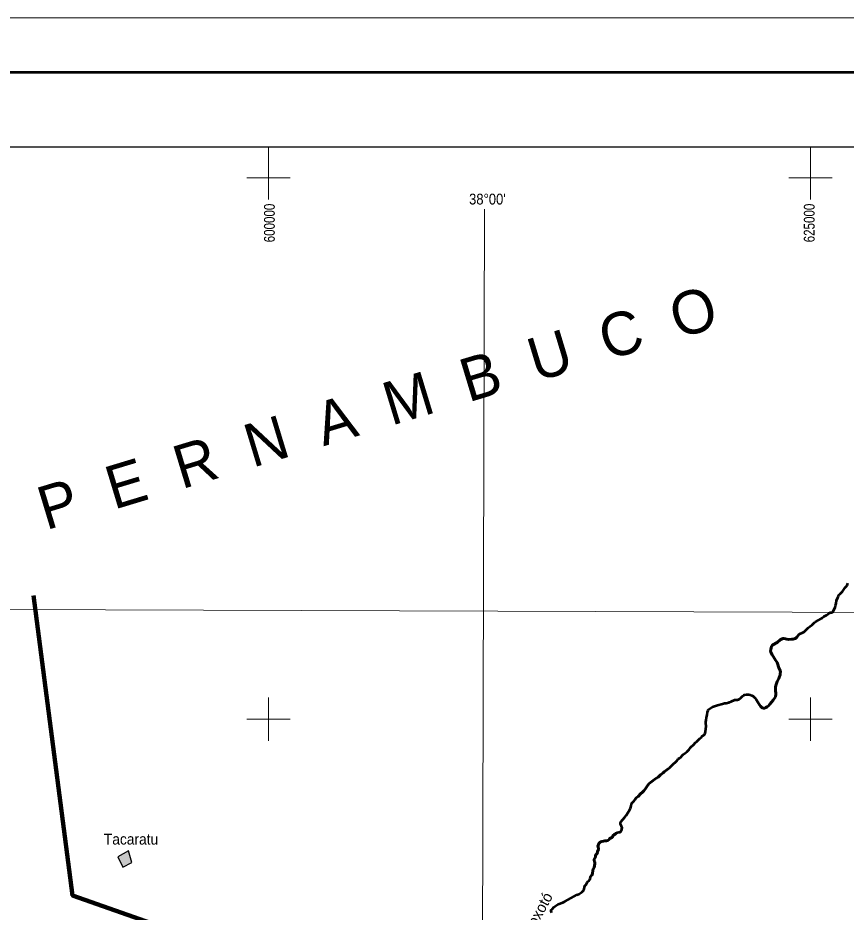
# Model space of a CAD drawing. Extents: x 553962 to 842807, y 8883888 to 9032388.
# Drawn here: x 588436 to 626649, y 8991098 to 9032388 of the extents above; entities that cross this region are included whole.
import ezdxf
from ezdxf.enums import TextEntityAlignment as Align

# ---------------------------------------------------------------- set-up
doc = ezdxf.new("R2010")
doc.units = 0
doc.header["$LTSCALE"] = 150
doc.linetypes.add('LONG_DASH_SHORT_DASH', pattern=[9.9, 6, -1.2, 1.5, -1.2])
for name, color, linetype, lineweight in [('1', 7, 'Continuous', 13), ('2', 7, 'Continuous', 13), ('21', 7, 'Continuous', 25), ('24', 7, 'Continuous', 25), ('3', 7, 'Continuous', 13), ('7', 7, 'LONG_DASH_SHORT_DASH', 60), ('9', 7, 'Continuous', 90)]:
    doc.layers.add(name, color=color, linetype=linetype, lineweight=lineweight)
for name, color, linetype in [('41', 7, 'Continuous'), ('42', 7, 'Continuous'), ('46', 7, 'Continuous'), ('47', 7, 'Continuous'), ('49', 7, 'Continuous')]:
    doc.layers.add(name, color=color, linetype=linetype)

msp = doc.modelspace()

# ---------------------------------------------------------------- hatches: boundary and pattern name
at = {"layer": '21'}
msp.add_hatch(color=256, dxfattribs=at).paths.add_polyline_path([(593047.1, 8993652.8), (593274.2, 8993173.1), (593688.7, 8993391.5), (593540, 8993932.9)])

# ---------------------------------------------------------------- linework, layer by layer
at = {"layer": '1'}
for points in [[(609971.9, 9023551.8), (609764.7, 8949706.7), (609734.2, 8939404.4)], [(565303.2, 9005146.6), (664889.8, 9004806.7), (719872.1, 9004543.9), (790635.8, 9004109)]]:
    msp.add_lwpolyline(points, dxfattribs=at)
at = {"layer": '2'}
for p, q in [((600000, 9024000), (600000, 9026438.8)), ((625000, 9024000), (625000, 9026438.8)), ((599000, 9025000), (601000, 9025000)), ((624000, 9025000), (626000, 9025000)), ((600000, 8999000), (600000, 9001000)), ((625000, 8999000), (625000, 9001000)), ((599000, 9000000), (601000, 9000000)), ((624000, 9000000), (626000, 9000000))]:
    msp.add_line(p, q, dxfattribs=at)
at = {"layer": '21'}
msp.add_lwpolyline([(593047.1, 8993652.8), (593274.2, 8993173.1), (593688.7, 8993391.5), (593540, 8993932.9)], close=True, dxfattribs=at)
at = {"layer": '24', "lineweight": 53}
for points in [[(626161, 9005249.2), (626188.6, 9005351.8), (626211.6, 9005488.2), (626262, 9005622), (626290.8, 9005686), (626318.1, 9005740.6), (626357.2, 9005784), (626440.5, 9005861.4), (626481.1, 9005905.8), (626516.3, 9005951), (626547.5, 9005998.1), (626576.5, 9006046.2), (626606.6, 9006087.7), (626651.3, 9006133.9), (626697.2, 9006185.8), (626721.1, 9006227.2), (626725, 9006288.4)], [(626020.3, 9004931.6), (626138.4, 9005165.4), (626161, 9005249.2)], [(624968.7, 9004287.4), (625077.4, 9004367.4), (625125.3, 9004407.4), (625196.1, 9004475.4), (625232, 9004503.4), (625369.3, 9004583.4), (625507, 9004648.4), (625552.2, 9004680.4), (625627.3, 9004743.4), (625747.5, 9004813.4), (625804.8, 9004859.3), (625863.6, 9004898.3), (625936.5, 9004925.7), (626020.3, 9004931.6)], [(622356.1, 9001071.6), (622438.9, 9000988.6), (622501.2, 9000910.6), (622651.6, 9000673.6), (622694.8, 9000613.6), (622741.9, 9000562.6), (622781.6, 9000528.6), (622838, 9000513.6), (622887.5, 9000510.6), (622903.5, 9000513.6), (622951.5, 9000538.6), (623008.3, 9000580.6), (623061.1, 9000626.5), (623124.5, 9000694.5), (623279.2, 9000880.5), (623385, 9001031.5), (623398.2, 9001059.5), (623411.2, 9001147.5), (623406.1, 9001224.5), (623394.5, 9001300.5), (623396.9, 9001485.5), (623407.8, 9001557.5), (623420.7, 9001604.5), (623474.8, 9001753.5), (623546.5, 9001882.5), (623566.5, 9001928.5), (623606.4, 9002057.5), (623614.4, 9002114.5), (623615.2, 9002180.5), (623603.6, 9002252.5), (623548.9, 9002380.5), (623488.7, 9002579.5), (623465.3, 9002623.5), (623431.2, 9002675.5), (623387.3, 9002730.5), (623302, 9002882.5), (623235.1, 9002973.5), (623183.3, 9003094.5), (623167.7, 9003160.5), (623170, 9003229.5), (623186.6, 9003301.5), (623210, 9003362.5), (623241.9, 9003412.5), (623274.8, 9003442.5), (623462.1, 9003547.5), (623608.8, 9003667.5), (623666.2, 9003700.5), (623727.2, 9003726.5), (623755.6, 9003733.5), (623782.5, 9003731.5), (623993.5, 9003691.5), (624127.2, 9003701.5), (624209, 9003698.5), (624301.4, 9003736.4), (624324.7, 9003751.4), (624377.4, 9003798.4), (624433, 9003873.4), (624469.5, 9003912.4), (624514.8, 9003941.4), (624628.9, 9003992.4), (624709.5, 9004038.4), (624743.9, 9004077.4), (624810.6, 9004137.4), (624900.3, 9004230.4), (624968, 9004288.4)], [(620148.3, 8999353.7), (620168.6, 8999417.7), (620186.8, 8999678.7), (620178.1, 8999819.7), (620178.5, 8999880.7), (620194.3, 8999957.7), (620208.2, 9000078.7), (620242.8, 9000202.7), (620252.9, 9000329.7), (620263.2, 9000378.7), (620280.1, 9000412.7), (620305.3, 9000447.7), (620344.5, 9000485.7), (620432.6, 9000539.7), (620488.9, 9000569.7), (620581.6, 9000610.7), (620710.5, 9000657.7), (620939.4, 9000718.7), (621042.2, 9000740.6), (621118.4, 9000748.6), (621242.2, 9000776.6), (621275.5, 9000790.6), (621342.1, 9000826.6), (621518.2, 9000894.6), (621561.1, 9000901.6), (621637.2, 9000903.6), (621689.6, 9000916.6), (621716.6, 9000931.6), (621774.6, 9000977.6), (621867.2, 9001066.6), (621924.7, 9001110.6), (621967.5, 9001129.6), (622048.6, 9001140.6), (622160.3, 9001143.6), (622215.2, 9001136.6), (622300.1, 9001105.6), (622356.1, 9001071.6)], [(616275, 8994855), (616299.8, 8994916), (616306.6, 8994947), (616309.5, 8994997), (616289.9, 8995061), (616239.9, 8995143), (616235.6, 8995179), (616237.4, 8995206), (616262.8, 8995260), (616352.4, 8995378.9), (616439.6, 8995482.9), (616497.8, 8995558.9), (616654.6, 8995808.9), (616704.2, 8995904.9), (616721.4, 8995949.9), (616734.9, 8996009.9), (616742.4, 8996094.9), (616755.2, 8996130.9), (616770.5, 8996150.9), (616865.5, 8996231.9), (616968.5, 8996369.9), (617050.4, 8996439.9), (617160.7, 8996559.9), (617252.1, 8996633.9), (617320.9, 8996701.9), (617376, 8996767.9), (617466.2, 8996912.9), (617553.7, 8997026.9), (617627.5, 8997088.9), (617747.7, 8997167.8), (617821.7, 8997231.8), (617864.4, 8997264.8), (617970.3, 8997332.8), (618086, 8997441.8), (618201.6, 8997530.8), (618257.2, 8997582.8), (618380.8, 8997669.8), (618495.1, 8997763.8), (618608.2, 8997867.8), (618687.2, 8997947.8), (618784.2, 8998026.8), (618847.8, 8998091.8), (618880.8, 8998148.8), (618904.8, 8998177.8), (618927, 8998194.8), (618960.5, 8998211.8), (619017, 8998253.8), (619099.7, 8998350.8), (619132.8, 8998382.8), (619235.9, 8998457.8), (619310.3, 8998518.8), (619402.8, 8998610.8), (619472.9, 8998704.8), (619501.7, 8998736.7), (619608.1, 8998826.7), (619700.3, 8998928.7), (619746.9, 8998966.7), (619804.3, 8999021.7), (619907.6, 8999106.7), (619970.1, 8999177.7), (620010.3, 8999215.7), (620083.8, 8999267.7), (620109.1, 8999292.7), (620148.3, 8999353.7), (620148.3, 8999353.7)], [(615088.6, 8993660), (615092.1, 8993720), (615153, 8993790), (615174.6, 8993852), (615175.1, 8993904), (615179, 8993921), (615187.3, 8993934), (615211.5, 8993958), (615228.8, 8993992), (615227.7, 8994030), (615203.4, 8994096), (615199.3, 8994145), (615206.1, 8994178), (615239.1, 8994264), (615295.5, 8994325), (615320, 8994336), (615520.9, 8994382), (615601.5, 8994383), (615661.9, 8994403), (615699.6, 8994431), (615734.4, 8994474), (615755.4, 8994494), (615812.3, 8994527), (615840.8, 8994550), (615864.4, 8994578), (615900.1, 8994637), (615919.4, 8994659), (615934.8, 8994670), (615988.9, 8994692), (616008.8, 8994710), (616037.3, 8994745), (616076.4, 8994766), (616108.6, 8994778), (616169.1, 8994784), (616218.9, 8994795), (616250.2, 8994821), (616275, 8994855)], [(613066.1, 8991064.2), (613044.7, 8991133.2), (613043.4, 8991164.2), (613047.9, 8991196.2), (613081.7, 8991228.2), (613169.8, 8991332.2), (613227.7, 8991376.2), (613365.8, 8991458.1), (613579.6, 8991541.1), (613666.1, 8991582.1), (614090.8, 8991825.1), (614218.9, 8991891.1), (614310.9, 8991932.1), (614460.7, 8992023.1), (614532.5, 8992094.1), (614543.7, 8992113.1), (614569, 8992177.1), (614582, 8992234.1), (614589.2, 8992317.1), (614668.2, 8992394.1), (614704.5, 8992469.1), (614728, 8992505.1), (614788.8, 8992558.1), (614827.1, 8992602.1), (614841.2, 8992635.1), (614852.2, 8992705.1), (614861.2, 8992733.1), (614874, 8992755.1), (614920, 8992803.1), (614934.5, 8992832.1), (614943.5, 8992879.1), (614957.9, 8993016), (614981.1, 8993081), (615017.2, 8993154), (615053.5, 8993321), (615053.4, 8993409), (615046.2, 8993436), (615020.3, 8993489), (615020.7, 8993515), (615030.5, 8993541), (615082.9, 8993633), (615082.9, 8993633), (615088.6, 8993660)]]:
    msp.add_lwpolyline(points, dxfattribs=at)
at = {"layer": '3'}
msp.add_lwpolyline([(842807.3, 9032387.8), (842807.3, 8883887.8), (553961.7, 8883887.8), (553961.7, 9032387.8)], close=True, dxfattribs=at)
at = {"layer": '3', "lineweight": 53}
msp.add_lwpolyline([(840307.3, 9029887.8), (840307.3, 8886387.8), (560211.7, 8886387.8), (560211.7, 9029887.8)], close=True, dxfattribs=at)
at = {"layer": '3', "lineweight": 25}
msp.add_lwpolyline([(563033.9, 9026438.8), (793061.1, 9026438.8), (793495.6, 8889836.8), (563468.3, 8889836.8)], close=True, dxfattribs=at)
at = {"layer": '7'}
for points in [[(622572.2, 9000798.7), (622651.6, 9000673.6), (622694.8, 9000613.6), (622741.9, 9000562.6), (622781.6, 9000528.6), (622838, 9000513.6), (622887.5, 9000510.6), (622903.5, 9000513.6), (622951.5, 9000538.6), (623008.3, 9000580.6), (623061.1, 9000626.5), (623124.5, 9000694.5), (623279.2, 9000880.5), (623385, 9001031.5), (623398.2, 9001059.5), (623411.2, 9001147.5), (623406.1, 9001224.5), (623394.5, 9001300.5), (623396.9, 9001485.5), (623407.8, 9001557.5), (623420.7, 9001604.5), (623474.8, 9001753.5), (623546.5, 9001882.5), (623566.5, 9001928.5), (623606.4, 9002057.5), (623614.4, 9002114.5), (623615.2, 9002180.5), (623603.6, 9002252.5), (623548.9, 9002380.5), (623488.7, 9002579.5), (623465.3, 9002623.5), (623431.2, 9002675.5), (623387.3, 9002730.5), (623302, 9002882.5), (623235.1, 9002973.5), (623183.3, 9003094.5), (623167.7, 9003160.5), (623170, 9003229.5), (623186.6, 9003301.5), (623210, 9003362.5), (623241.9, 9003412.5), (623274.8, 9003442.5), (623462.1, 9003547.5), (623608.8, 9003667.5), (623666.2, 9003700.5), (623727.2, 9003726.5), (623755.6, 9003733.5), (623782.5, 9003731.5), (623993.5, 9003691.5), (624127.2, 9003701.5), (624209, 9003698.5), (624301.4, 9003736.4), (624324.7, 9003751.4), (624377.4, 9003798.4), (624433, 9003873.4), (624469.5, 9003912.4), (624514.8, 9003941.4)], [(616899, 8996276.8), (616968.5, 8996369.9), (617050.4, 8996439.9), (617160.7, 8996559.9), (617252.1, 8996633.9), (617320.9, 8996701.9), (617376, 8996767.9), (617466.2, 8996912.9), (617553.7, 8997026.9), (617627.5, 8997088.9), (617747.7, 8997167.8), (617821.7, 8997231.8), (617864.4, 8997264.8), (617970.3, 8997332.8), (618086, 8997441.8), (618201.6, 8997530.8), (618257.2, 8997582.8), (618380.8, 8997669.8), (618437.7, 8997716.6)], [(615088.6, 8993660), (615092.1, 8993720), (615153, 8993790), (615174.6, 8993852), (615175.1, 8993904), (615179, 8993921), (615187.3, 8993934), (615211.5, 8993958), (615228.8, 8993992), (615227.7, 8994030), (615203.4, 8994096), (615199.3, 8994145), (615206.1, 8994178), (615239.1, 8994264), (615295.5, 8994325), (615320, 8994336), (615520.9, 8994382), (615601.5, 8994383), (615661.9, 8994403), (615699.6, 8994431), (615734.4, 8994474), (615755.4, 8994494), (615812.3, 8994527), (615840.8, 8994550), (615864.4, 8994578), (615900.1, 8994637), (615919.4, 8994659), (615934.8, 8994670), (615988.9, 8994692), (616008.8, 8994710), (616037.3, 8994745)], [(614923.2, 8992809.3), (614934.5, 8992832.1), (614943.5, 8992879.1), (614957.9, 8993016), (614981.1, 8993081), (615017.2, 8993154), (615053.5, 8993321), (615053.4, 8993409), (615046.2, 8993436), (615020.3, 8993489), (615020.7, 8993515), (615030.5, 8993541), (615082.9, 8993633), (615082.9, 8993633), (615088.6, 8993660)]]:
    msp.add_lwpolyline(points, dxfattribs=at)
at = {"layer": '9'}
msp.add_lwpolyline([(605873.8, 8986618.4), (590956.6, 8991866.7), (589163, 9005713.7)], dxfattribs=at)

# ---------------------------------------------------------------- texts
at = {"layer": '41', "width": 0.95}
msp.add_text('Tacaratu', height=500, dxfattribs=at).set_placement((592402.2, 8994216.5))
at = {"layer": '42'}
msp.add_text('P  E  R  N  A  M  B  U  C  O', height=2000, rotation=16.855, dxfattribs=at).set_placement((589730.9, 9008723.5))
at = {"layer": '46', "width": 0.9}
msp.add_text("38°00'", height=500, dxfattribs=at).set_placement((610099.9, 9023770.4), align=Align.CENTER)
at = {"layer": '47', "width": 0.8}
for s, p in [('600000', (600290.6, 9022917.4)), ('625000', (625197.3, 9022917.4))]:
    msp.add_text(s, height=500, rotation=90, dxfattribs=at).set_placement(p, align=Align.CENTER)
at = {"layer": '49'}
msp.add_text('Rio Moxotó', height=500, rotation=61.364, dxfattribs=at).set_placement((612325.1, 8990347.9), align=Align.CENTER)

doc.saveas('drawing.dxf')
